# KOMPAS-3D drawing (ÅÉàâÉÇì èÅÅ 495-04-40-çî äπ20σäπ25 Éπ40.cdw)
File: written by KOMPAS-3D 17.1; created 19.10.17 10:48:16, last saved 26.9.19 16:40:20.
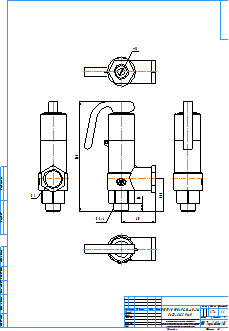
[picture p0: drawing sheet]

Sheet 1: A2, portrait

Title block, sheet 1: name: ПРЕГРАН КПП 495-04-40-ЗМ / Ду20хДу25 Ру40; material: Сталь 20  ГОСТ 1050-2013; mass: 1,74; sheets: 1; sheet format: A2; stored path: C:\Users\kka\KOMPAS_Work\!Trash\Прегран КПП 495\ПРЕГРАН КПП 495-04-40-ЗМ\KOMPAS 2D\Прегран КПП 495 Ду20хДу25 Ру40.cdw

Views: Спереди 6, Проекционный вид 7, Проекционный вид 8, Проекционный вид 9, Проекционный вид 10
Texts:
  kka
  adl
  Рама для чертежей
  Лит-Масса-Масштаб
  Материал-Предприятие
  Масштаб
  Изм.
  Лист
  № докум.
  Подп.
  Дата
  Лит.
  Разраб.
  Пров.
  Т.контр.
  Листов
  Внимание! Данный продукт является объектом авторского права ООО «Торговый Дом АДЛ».
  Запрещается изменение, копирование, распространение
  (в том числе путем копирования на другие сайты и ресурсы в Интернете)
  или любое иное использование информации и объектов без предварительного
  согласия правообладателя (ООО «Торговый Дом АДЛ»).
  Н.контр.
  Утв.
  ООО "Торговый дом АДЛ"
  Изменение
  Номер документа
  Подпись
  Обозначение документа
  Наименование изделия
  Масса изделия по ГОСТ 2.109-73
  Порядковый номер листа
  Общее количество листов в документе
  Характер работы, выполненной лицом, подписавшим документ
  Наименование или индекс предприятия, выпускающего документ
  Инв. № подл.
  Подп. и дата
  Взам. инв. №
  Инв. № дубл.
  Инвентарный номер подлинника по ГОСТ 2.501-68
  Подпись принявшего подлинник в отдел технической документации
  Инвентарный номер подлинника, взамен которого выпущен данный подлинник
  Инвентарный номер дубликата по ГОСТ 2.502-68
  Подпись принявшего дубликат в отдел технической документации
  Справ. №
  Перв. примен.
  Обозначение документа, взамен или на основании которого выпущен данный документ
  Обозначение документа, в котором впервые записан данный документ
  Подпись лица, копировавшего чертеж
  Обозначение формата листа
  !Рама для чертежа
Dimensions and other numbers on the sheet: 58,5; 15; 60; 196; 13; 1,74; 1:1; 1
